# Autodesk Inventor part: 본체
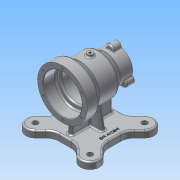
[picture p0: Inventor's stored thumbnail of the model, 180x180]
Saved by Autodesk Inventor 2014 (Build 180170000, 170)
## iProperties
Created: 2017-03
Part Number: 본체
Material: 알루미늄 6061
Document SubType Name: Modeling
Designer: NET
Density: 2.71 g/cm^3
Appearance: 알루미늄 - 평지
Mass: 1008.06 g
Surface Area: 842.102 cm^2
Volume: 371.977 cm^3
Author: NET
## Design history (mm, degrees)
sketch "스케치1"
  geometry: L1 (-50, 0)-(-50, 45); L2 (-50, 45)-(-30, 45); L3 (-30, 45)-(-19, 36); L4 (-19, 36)-(15, 36); L5 (50, 27.5)-(50, 0); L6 (50, 0)-(-50, 0); L7 (27, 27.5)-(50, 27.5); L8 (27, 27.5)-(15, 36); 2 further points
  constraints: 16 end point, 4 parallel, 1 coincident, 1 midpoint, 1 perpendicular, 1 vertical
  dimensions: "d0" = 90 diameter of L2 L6; "d1" = 20 distance from line of L1 L2.end; "d2" = 31 distance from line of L1 L3.end; "d3" = 65 distance from line of L1 L4.end; "d4" = 100 distance between parallel lines of L5 L1; "d6" = 72 diameter of L4 L6; "d7" = 55 diameter of L7 L6; "d8" = 23 distance from line of L5 L7.start
revolve "회전1" sketch "스케치1" stored, may be unused: angle "d9" = 90 deg
sketch "스케치2"
  geometry: L1 (-50, 35)-(-30, 35); L2 (-27, 32)-(-27, 29); L3 (-24, 26)-(17, 26); L4 (20, 23)-(20, 20.5); L5 (23, 17.5)-(50, 17.5); L6 (50, 17.5)-(50, 0); L7 (50, 0)-(-50, 0); L8 (-50, 0)-(-50, 35); L9 (-50, -45)-(-50, 45) reference; A1 r 3 centre (-30, 32) between (-27, 32) and (-30, 35); A2 r 3 centre (-24, 29) between (-27, 29) and (-24, 26); A3 r 3 centre (17, 23) between (20, 23) and (17, 26); A4 r 3 centre (23, 20.5) between (20, 20.5) and (23, 17.5); 5 further points
  constraints: 16 end point, 8 point on circle, 8 point on line, 8 tangent, 5 parallel, 4 centre point, 3 equal radius, 1 horizontal, 1 horizontal alignment, 1 midpoint, 1 perpendicular, 1 vertical
  dimensions: "d10" = 23 distance between parallel lines of L2 L8; "d11" = 30 distance between parallel lines of L6 L4; "d12" = 47 distance of point (-27, 26) point (20, 26); "d13" = 70 diameter of L1 L7; "d14" = 52 diameter of L3 L7; "d15" = 35 diameter of L5 L7; "d17" = 3 radius of A1
revolve "회전2" sketch "스케치2" stored, may be unused: angle "d16" = 90 deg
fillet "모깎기1" dims "d18" = 3
sketch "스케치3"
  geometry: C1 r 17.5 at (0, 0) reference
sketch "스케치4"
  geometry: L1 (0, -27.5)-(0, -16.662); L2 (7, -27.5)-(7, -16.662); L3 (-7, -16.662)-(-7, -27.5); C1 r 17.5 at (0, 0) reference; A1 r 7 centre (0, -27.5) between (-7, -27.5) and (7, -27.5); A2 r 7 centre (0, -16.662) between (7, -16.662) and (-7, -16.662); 2 further points
  constraints: 8 end point, 4 point on circle, 4 tangent, 2 centre point, 2 vertical alignment, 1 midpoint, 1 parallel, 1 vertical, 1 other
  dimensions: "d19" = 7 radius of A1
extrude "돌출1" join sketch "스케치4" distance "d20" = 15; taper "d21" = 0 deg
extrude "돌출2" cut sketch "스케치3" distance "d25" = 15; taper "d26" = 0 deg
fillet "모깎기2" dims "d27" = 3
fillet "모깎기3" dims "d28" = 1
hole "구멍1" diameter "d31" = 3.242; stored, may be unused: countersink angle "d35" = 90 deg, drill point angle "d37" = 118 deg; dims "d29" = 10, "d30" = 10, "d32" = 9, "d33" = 4, "d34" = 2, "d36" = 11
sketch "스케치6"
  geometry: C1 r 35 at (0, 0) reference; 1 further point
  constraints: 1 vertical alignment
  dimensions: "d41" = 40 distance of point (0, 40) C1.centre
hole "구멍2" sketch "스케치6" at (0, 40) diameter "d42" = 3.242; stored, may be unused: countersink angle "d46" = 90 deg, drill point angle "d48" = 118 deg; dims "d43" = 9, "d44" = 4, "d45" = 2, "d47" = 11
node "작업 평면1"
sketch "스케치7"
  geometry: L1 (45, -45)-(-45, -45); L2 (-45, -45)-(-45, 45); L3 (-45, 45)-(45, 45); L4 (45, 45)-(45, -45); L5 (45, -45)-(-45, 45); L6 (-45, -45)-(45, 45); L7 (6.944, 6.944)-(49.497, 49.497); L8 (18.965, -5.077)-(61.518, 37.477); L9 (37.477, 61.518)-(-5.077, 18.965); A1 r 17 centre (6.944, 6.944) between (-5.077, 18.965) and (18.965, -5.077); A2 r 17 centre (49.497, 49.497) between (61.518, 37.477) and (37.477, 61.518); 2 further points
  constraints: 20 end point, 4 point on circle, 4 tangent, 3 midpoint, 3 parallel, 2 centre point, 2 point on line, 1 horizontal, 1 perpendicular
  dimensions: "d53" = 90 distance between parallel lines of L1 L3; "d54" = 90 distance between parallel lines of L4 L2; "d55" = 70 distance of point (0, 0) L7.end; "d56" = 34 distance between parallel lines of L8 L9
extrude "돌출3" join sketch "스케치7" distance "d57" = 12; taper "d58" = 0 deg
extrude "돌출4" join sketch "스케치7" distance "d59" = 12; taper "d60" = 0 deg
fillet "모깎기4" dims "d64" = 25
hole "구멍3" diameter "d67" = 10; stored, may be unused: countersink angle "d71" = 90 deg, drill point angle "d73" = 118 deg; dims "d65" = 10, "d66" = 10, "d68" = 9, "d69" = 4, "d70" = 2, "d72" = 11
sketch "스케치8"
  geometry: L1 (4, -37)-(-4, -37); L2 (-4, -37)-(-4, 37); L3 (-4, 37)-(4, 37); L4 (4, 37)-(4, -37); L5 (4, -37)-(-4, 37); L6 (-4, -37)-(4, 37); L7 (25, -4)-(-25, -4); L8 (-25, -4)-(-25, 4); L9 (-25, 4)-(25, 4); L10 (25, 4)-(25, -4); L11 (25, -4)-(-25, 4); L12 (-25, -4)-(25, 4); 1 further point
  constraints: 24 end point, 4 midpoint, 4 parallel, 2 horizontal, 2 perpendicular
  dimensions: "d77" = 37 distance from line of point (0, 0) L1; "d78" = 37 distance from line of L3 point (0, 0) (derived); "d79" = 8 distance between parallel lines of L4 L2; "d80" = 25 distance from line of point (0, 0) L8; "d81" = 8 distance between parallel lines of L7 L9
extrude "돌출5" join sketch "스케치8" stored distance "d82" = 12; taper "d83" = 0 deg
feature "면 기울기1" dims angle "d84" = 10 deg
fillet "모깎기5" dims "d85" = 3
fillet "모깎기6" dims "d86" = 3
fillet "모깎기7" dims "d87" = 3
node "작업 평면2"
sketch "스케치9"
  geometry: L1 (45, -50)-(-45, -50) reference; C1 r 5 at (0, 0); 1 further point
  constraints: 1 centre point, 1 coincident
  dimensions: "d89" = 10 diameter of C1; "d90" = 50 distance from line of L1 C1.centre
extrude "돌출6" join sketch "스케치9" stored distance "d91" = 12; taper "d92" = 0 deg
fillet "모깎기8" dims "d93" = 3
hole "구멍4" diameter "d96" = 4.134; stored, may be unused: countersink angle "d100" = 90 deg, drill point angle "d102" = 118 deg; dims "d94" = 10, "d95" = 10, "d97" = 30, "d98" = 4, "d99" = 2, "d101" = 30
sketch "스케치10"
  geometry: 2 further points
  constraints: 1 horizontal alignment, 1 other
  dimensions: "d103" = 35 distance of point (35, 0) point (0, 0)
feature "엠보싱1" sketch "스케치10" dims "d0" = 90, "d1" = 20, "d2" = 31, "d3" = 65, "d4" = 100, "d6" = 72, "d7" = 55, "d8" = 23, "d104" = 0.5, "d105" = 0
chamfer "모따기1" distance "d106" = 1; stored, may be unused: second distance "d107" = 2, angle "d108" = 45 deg
node "솔리드1"
pattern_circular "원형 패턴1" dims angle "d23" = 360 deg
pattern_circular "원형 패턴2" dims angle "d39" = 360 deg
pattern_circular "원형 패턴3" dims angle "d50" = 360 deg
pattern_circular "원형 패턴4" dims angle "d62" = 360 deg
pattern_circular "원형 패턴5" dims angle "d75" = 360 deg
other parameters: "d52" = -82
